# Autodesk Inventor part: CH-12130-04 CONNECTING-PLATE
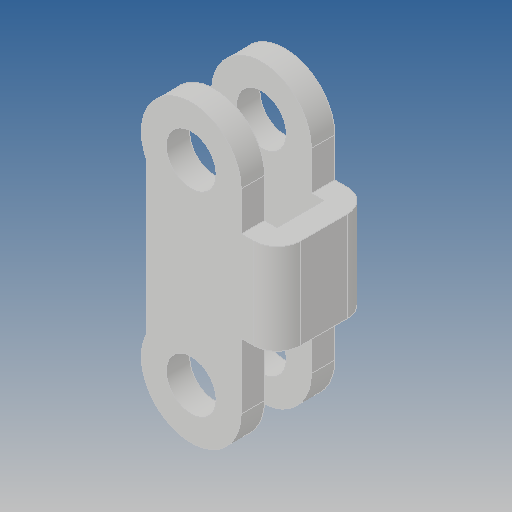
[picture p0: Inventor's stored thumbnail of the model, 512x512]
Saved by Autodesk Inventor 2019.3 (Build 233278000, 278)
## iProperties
Created: 2017-11
Part Number: CH-12130-04 CONNECTING-PLATE
Material: Ogólny
Document SubType Name: Modeling
Designer: Admin
Density: 1 g/cm^3
Appearance: Domyślna
Author: Admin
Revision Number: ÈÎºÎ
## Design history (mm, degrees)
feature "Ô²½Ç1"
node "Bryła1"
